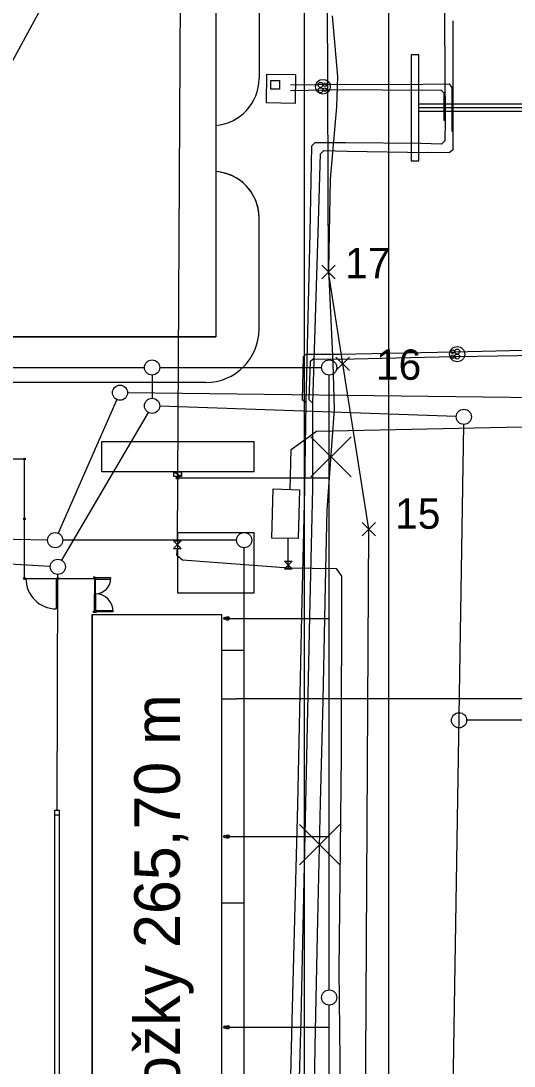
# Model space of a CAD drawing. Extents: x -264095 to -263675, y -1242370 to -1242073.
# Drawn here: x -263972.3 to -263939.8, y -1242227.5 to -1242158.7 of the extents above; entities that cross this region are included whole.
import ezdxf

# ---------------------------------------------------------------- set-up
doc = ezdxf.new("R2010")
doc.units = 0
for name, color, linetype in [('BODY', 7, 'Continuous'), ('KFA_2D_JESTVUJUCE_IS_DSP', 7, 'Continuous'), ('KFA_2D_SITUACIA_DSP', 7, 'Continuous'), ('ORANGE_KABEL_NOVA_TRASA', 7, 'Continuous'), ('POPIS', 7, 'Continuous'), ('Pripojka_NN_pre_ORANGE_vysielac_povodna_trasa', 7, 'Continuous')]:
    doc.layers.add(name, color=color, linetype=linetype)

msp = doc.modelspace()

# ---------------------------------------------------------------- linework, layer by layer
at = {"layer": 'BODY'}
for p, q in [((-263952.482, -1242175.643), (-263951.598, -1242174.759)), ((-263951.598, -1242175.643), (-263952.482, -1242174.759)), ((-263951.549, -1242181.696), (-263950.665, -1242180.812)), ((-263950.665, -1242181.696), (-263951.549, -1242180.812)), ((-263949.826, -1242192.601), (-263948.942, -1242191.717)), ((-263948.942, -1242192.601), (-263949.826, -1242191.717))]:
    msp.add_line(p, q, dxfattribs=at)
at = {"layer": 'KFA_2D_JESTVUJUCE_IS_DSP'}
for p, q in [((-263961.582, -1242115.554), (-263961.999, -1242192.922)), ((-263944.386, -1242147.884), (-263944.412, -1242158.664)), ((-263944.412, -1242158.664), (-263944.352, -1242165.249)), ((-263943.853, -1242158.652), (-263943.849, -1242165.958)), ((-263956.13, -1242162.18), (-263956.156, -1242164.04)), ((-263954.192, -1242162.207), (-263956.13, -1242162.18)), ((-263954.218, -1242164.067), (-263954.192, -1242162.207)), ((-263955.831, -1242163.152), (-263955.831, -1242162.573)), ((-263955.831, -1242162.573), (-263955.28, -1242162.573)), ((-263955.28, -1242162.573), (-263955.28, -1242163.152)), ((-263951.019, -1242162.854), (-263954.543, -1242162.888)), ((-263951.019, -1242162.854), (-263945.83, -1242162.832)), ((-263945.83, -1242162.832), (-263944.071, -1242162.801)), ((-263943.916, -1242163.012), (-263944.071, -1242162.801)), ((-263955.28, -1242163.152), (-263955.831, -1242163.152)), ((-263951.079, -1242163.196), (-263954.539, -1242163.255)), ((-263945.899, -1242163.231), (-263951.079, -1242163.196)), ((-263944.614, -1242163.211), (-263945.899, -1242163.231)), ((-263944.447, -1242163.393), (-263944.614, -1242163.211)), ((-263944.447, -1242163.393), (-263944.442, -1242165.164)), ((-263943.914, -1242163.012), (-263943.913, -1242165.895)), ((-263956.156, -1242164.04), (-263954.218, -1242164.067)), ((-263944.442, -1242165.164), (-263944.352, -1242165.249)), ((-263944.442, -1242165.164), (-263944.442, -1242165.164)), ((-263944.352, -1242165.249), (-263944.379, -1242166.564)), ((-263943.913, -1242165.895), (-263943.849, -1242165.958)), ((-263943.913, -1242165.895), (-263943.913, -1242165.895)), ((-263943.849, -1242165.958), (-263943.861, -1242167.143)), ((-263953.167, -1242166.907), (-263953.276, -1242172.621)), ((-263952.942, -1242166.698), (-263953.167, -1242166.907)), ((-263950.896, -1242166.694), (-263952.942, -1242166.698)), ((-263945.968, -1242166.741), (-263950.896, -1242166.694)), ((-263944.61, -1242166.777), (-263945.968, -1242166.741)), ((-263944.379, -1242166.564), (-263944.61, -1242166.777)), ((-263952.715, -1242172.612), (-263952.57, -1242167.416)), ((-263952.57, -1242167.416), (-263952.361, -1242167.2)), ((-263952.361, -1242167.2), (-263950.803, -1242167.244)), ((-263950.803, -1242167.244), (-263945.525, -1242167.325)), ((-263944.087, -1242167.347), (-263945.525, -1242167.325)), ((-263943.861, -1242167.143), (-263944.087, -1242167.347)), ((-263953.276, -1242172.621), (-263953.528, -1242183.799)), ((-263953.067, -1242183.845), (-263952.715, -1242172.612)), ((-263943.779, -1242180.456), (-263932.226, -1242180.187)), ((-263953.71, -1242180.8), (-263953.774, -1242183.629)), ((-263953.71, -1242180.8), (-263953.518, -1242180.617)), ((-263953.518, -1242180.617), (-263951.311, -1242180.614)), ((-263951.311, -1242180.614), (-263943.779, -1242180.456)), ((-263951.265, -1242180.941), (-263943.848, -1242180.778)), ((-263943.848, -1242180.778), (-263943.567, -1242180.776)), ((-263943.567, -1242180.776), (-263932.313, -1242180.597)), ((-263953.31, -1242183.629), (-263953.231, -1242181.09)), ((-263953.231, -1242181.09), (-263953.049, -1242180.917)), ((-263953.049, -1242180.917), (-263951.265, -1242180.941)), ((-263965.974, -1242183.616), (-263969.841, -1242192.426)), ((-263923.234, -1242183.668), (-263965.273, -1242183.165)), ((-263953.528, -1242183.799), (-263953.774, -1242183.629)), ((-263953.067, -1242183.845), (-263953.31, -1242183.629)), ((-263943.628, -1242184.728), (-263963.161, -1242184.046)), ((-263953.528, -1242183.799), (-263953.63, -1242189.514)), ((-263953.083, -1242189.456), (-263953.067, -1242183.845)), ((-263963.914, -1242184.46), (-263969.615, -1242194.201)), ((-263954.509, -1242186.913), (-263952.832, -1242185.692)), ((-263952.832, -1242185.692), (-263937.488, -1242185.363)), ((-263943.946, -1242236.311), (-263943.136, -1242185.245)), ((-263954.57, -1242189.535), (-263954.509, -1242186.913)), ((-263955.775, -1242192.739), (-263955.679, -1242189.503)), ((-263955.679, -1242189.503), (-263953.955, -1242189.552)), ((-263953.955, -1242189.552), (-263954.033, -1242192.766)), ((-263953.63, -1242189.514), (-263953.822, -1242197.849)), ((-263953.266, -1242197.902), (-263953.083, -1242189.456)), ((-263970.367, -1242194.605), (-264044.102, -1242190.483)), ((-263970.542, -1242192.875), (-264044.328, -1242191.641)), ((-263962.251, -1242192.922), (-263961.751, -1242192.922)), ((-263961.751, -1242192.922), (-263962.251, -1242193.422)), ((-263961.751, -1242193.422), (-263962.251, -1242192.922)), ((-263954.033, -1242192.766), (-263955.775, -1242192.739)), ((-263954.693, -1242194.518), (-263954.696, -1242192.756)), ((-263962.251, -1242193.422), (-263961.751, -1242193.422)), ((-263962.017, -1242193.422), (-263962.046, -1242193.838)), ((-263962.046, -1242193.838), (-263961.65, -1242194.164)), ((-263961.65, -1242194.164), (-263954.663, -1242194.7)), ((-263954.943, -1242194.268), (-263954.443, -1242194.268)), ((-263954.443, -1242194.268), (-263954.943, -1242194.768)), ((-263954.443, -1242194.768), (-263954.943, -1242194.268)), ((-263954.663, -1242194.7), (-263954.693, -1242194.518)), ((-263954.943, -1242194.768), (-263954.443, -1242194.768)), ((-263954.663, -1242194.7), (-263951.539, -1242194.754)), ((-263951.539, -1242194.754), (-263951.176, -1242195.243)), ((-263951.176, -1242195.243), (-263951.207, -1242207.105)), ((-263953.822, -1242197.849), (-263954.091, -1242210.31)), ((-263953.525, -1242210.24), (-263953.266, -1242197.902)), ((-263951.207, -1242207.105), (-263951.356, -1242221.201)), ((-263954.091, -1242210.31), (-263954.451, -1242224.536)), ((-263953.851, -1242224.476), (-263953.525, -1242210.24)), ((-263951.356, -1242221.201), (-263951.228, -1242233.09)), ((-263954.451, -1242224.536), (-263954.692, -1242233.447)), ((-263954.106, -1242234.073), (-263953.851, -1242224.476))]:
    msp.add_line(p, q, dxfattribs=at)
for centre, radius in [((-263952.413, -1242162.992), 0.487), ((-263952.568, -1242162.867), 0.164), ((-263952.284, -1242162.851), 0.122), ((-263952.568, -1242163.22), 0.164), ((-263952.284, -1242163.187), 0.122), ((-263943.568, -1242180.617), 0.496), ((-263943.848, -1242180.461), 0.122), ((-263943.848, -1242180.778), 0.122), ((-263943.567, -1242180.445), 0.164), ((-263943.567, -1242180.776), 0.164), ((-263965.773, -1242183.159), 0.5), ((-263963.661, -1242184.028), 0.5), ((-263943.128, -1242184.745), 0.5), ((-263970.042, -1242192.883), 0.5), ((-263969.868, -1242194.633), 0.5)]:
    msp.add_circle(centre, radius, dxfattribs=at)
at = {"layer": 'KFA_2D_SITUACIA_DSP'}
for p, q in [((-263959.468, -1242072.525), (-263959.468, -1242179.482)), ((-263948.093, -1242087.901), (-263948.093, -1242241.458)), ((-263953.617, -1242244.458), (-263953.617, -1242093.307)), ((-263956.618, -1242127.418), (-263956.618, -1242162.449)), ((-263918.489, -1242164.132), (-263946.093, -1242164.132)), ((-263918.593, -1242164.382), (-263946.093, -1242164.382)), ((-263918.696, -1242164.632), (-263946.093, -1242164.632)), ((-263959.468, -1242165.549), (-263959.468, -1242165.549)), ((-263959.467, -1242168.582), (-263959.467, -1242168.582)), ((-263956.618, -1242178.982), (-263956.618, -1242171.645)), ((-264095.114, -1242179.482), (-263959.468, -1242179.482)), ((-263959.468, -1242179.482), (-264095.114, -1242179.482)), ((-263959.468, -1242179.482), (-264077.23, -1242179.482)), ((-263956.618, -1242178.982), (-263956.618, -1242178.982)), ((-264013.161, -1242181.5), (-263964.161, -1242181.5)), ((-263963.161, -1242181.5), (-263952.5, -1242181.5)), ((-263963.661, -1242182), (-263963.661, -1242183.528)), ((-263952, -1242222.527), (-263952, -1242182)), ((-263960.118, -1242182.482), (-264034.158, -1242182.482)), ((-263972.068, -1242187.532), (-264095.114, -1242187.532)), ((-263972.128, -1242187.532), (-263972.008, -1242187.532)), ((-263972.068, -1242187.592), (-263972.068, -1242187.472)), ((-263972.068, -1242195.407), (-263972.068, -1242187.532)), ((-263962.218, -1242188.382), (-263961.718, -1242188.382)), ((-263962.218, -1242188.672), (-263962.218, -1242188.382)), ((-263962.218, -1242188.382), (-263961.718, -1242188.672)), ((-263962.218, -1242188.382), (-263961.718, -1242188.672)), ((-263961.718, -1242188.382), (-263962.218, -1242188.382)), ((-263961.718, -1242188.382), (-263961.718, -1242188.672)), ((-263961.718, -1242188.672), (-263961.718, -1242188.382)), ((-263961.718, -1242188.672), (-263962.218, -1242188.672)), ((-263961.868, -1242188.772), (-263952, -1242188.772)), ((-263972.128, -1242191.47), (-263972.008, -1242191.47)), ((-263972.068, -1242191.41), (-263972.068, -1242191.53)), ((-263958.097, -1242192.883), (-263969.542, -1242192.883)), ((-263957.597, -1242243.932), (-263957.597, -1242193.383)), ((-263969.921, -1242210.683), (-263969.869, -1242195.133)), ((-263967.413, -1242195.307), (-263967.513, -1242195.307)), ((-263967.513, -1242195.307), (-263967.513, -1242195.407)), ((-263967.425, -1242195.32), (-263967.5, -1242195.32)), ((-263967.5, -1242195.32), (-263967.5, -1242195.395)), ((-263967.425, -1242195.395), (-263967.425, -1242195.32)), ((-263967.425, -1242195.395), (-263967.425, -1242195.345)), ((-263967.425, -1242195.345), (-263967.325, -1242195.345)), ((-263967.413, -1242195.407), (-263967.413, -1242195.307)), ((-263967.413, -1242195.357), (-263967.363, -1242195.357)), ((-263967.363, -1242195.357), (-263967.363, -1242195.457)), ((-263967.325, -1242195.345), (-263967.325, -1242195.37)), ((-263972.068, -1242195.407), (-263967.418, -1242195.407)), ((-263969.968, -1242195.407), (-263969.968, -1242197.407)), ((-263967.513, -1242195.407), (-263967.413, -1242195.407)), ((-263967.5, -1242195.395), (-263967.425, -1242195.395)), ((-263967.463, -1242195.407), (-263967.463, -1242196.395)), ((-263967.388, -1242195.407), (-263967.463, -1242195.407)), ((-263967.388, -1242196.395), (-263967.388, -1242195.407)), ((-263967.363, -1242195.457), (-263967.388, -1242195.457)), ((-263966.388, -1242195.371), (-263967.375, -1242195.37)), ((-263967.375, -1242195.37), (-263967.375, -1242195.445)), ((-263967.375, -1242195.445), (-263966.388, -1242195.446)), ((-263967.463, -1242197.557), (-263967.463, -1242196.42)), ((-263967.388, -1242196.42), (-263967.388, -1242197.557)), ((-263967.593, -1242252.182), (-263967.593, -1242197.782)), ((-263967.593, -1242197.782), (-263959.093, -1242197.782)), ((-263967.593, -1242197.782), (-263959.097, -1242197.782)), ((-263967.593, -1242252.182), (-263967.593, -1242197.782)), ((-263967.513, -1242197.557), (-263967.413, -1242197.557)), ((-263967.513, -1242197.657), (-263967.513, -1242197.557)), ((-263967.413, -1242197.657), (-263967.513, -1242197.657)), ((-263967.5, -1242197.57), (-263967.425, -1242197.57)), ((-263967.5, -1242197.645), (-263967.5, -1242197.57)), ((-263967.425, -1242197.645), (-263967.5, -1242197.645)), ((-263967.478, -1242197.782), (-263967.358, -1242197.782)), ((-263967.388, -1242197.557), (-263967.463, -1242197.557)), ((-263967.425, -1242197.57), (-263967.425, -1242197.62)), ((-263967.425, -1242197.57), (-263967.425, -1242197.645)), ((-263967.425, -1242197.62), (-263967.325, -1242197.62)), ((-263967.413, -1242197.557), (-263967.413, -1242197.657)), ((-263967.413, -1242197.607), (-263967.363, -1242197.607)), ((-263967.363, -1242197.507), (-263967.388, -1242197.507)), ((-263967.375, -1242197.52), (-263966.238, -1242197.52)), ((-263967.375, -1242197.595), (-263967.375, -1242197.52)), ((-263966.238, -1242197.595), (-263967.375, -1242197.595)), ((-263967.363, -1242197.607), (-263967.363, -1242197.507)), ((-263967.325, -1242197.62), (-263967.325, -1242197.595)), ((-263959.097, -1242197.782), (-263959.093, -1242252.182)), ((-263959.093, -1242197.782), (-263959.093, -1242252.182)), ((-263958.799, -1242197.962), (-263958.762, -1242197.962)), ((-263958.799, -1242198.102), (-263958.762, -1242198.102)), ((-263958.762, -1242197.962), (-263958.742, -1242197.942)), ((-263958.762, -1242198.102), (-263958.742, -1242198.122)), ((-263958.742, -1242197.942), (-263958.637, -1242197.942)), ((-263958.575, -1242198.032), (-263952, -1242198.032)), ((-263958.742, -1242198.122), (-263958.637, -1242198.122)), ((-263959.097, -1242200.132), (-263957.597, -1242200.132)), ((-263959.097, -1242203.332), (-263958.097, -1242203.332)), ((-263924.893, -1242203.332), (-263958.097, -1242203.332)), ((-263938.393, -1242204.752), (-263942.945, -1242204.752)), ((-263970.071, -1242210.684), (-263969.77, -1242210.682)), ((-263970.07, -1242239.282), (-263970.071, -1242210.684)), ((-263970.071, -1242210.983), (-263969.771, -1242210.985)), ((-263969.77, -1242210.682), (-263969.77, -1242239.282)), ((-263958.799, -1242212.337), (-263958.762, -1242212.337)), ((-263958.799, -1242212.477), (-263958.762, -1242212.477)), ((-263958.762, -1242212.337), (-263958.742, -1242212.317)), ((-263958.762, -1242212.477), (-263958.742, -1242212.497)), ((-263958.742, -1242212.317), (-263958.637, -1242212.317)), ((-263958.742, -1242212.497), (-263958.637, -1242212.497)), ((-263958.575, -1242212.407), (-263952, -1242212.407)), ((-263959.097, -1242216.782), (-263957.597, -1242216.782)), ((-263952, -1242251.432), (-263952, -1242223.527)), ((-263958.799, -1242224.912), (-263958.762, -1242224.912)), ((-263958.762, -1242224.912), (-263958.742, -1242224.892)), ((-263958.742, -1242224.892), (-263958.637, -1242224.892)), ((-263958.575, -1242224.982), (-263952, -1242224.982)), ((-263958.799, -1242225.052), (-263958.762, -1242225.052)), ((-263958.762, -1242225.052), (-263958.742, -1242225.072)), ((-263958.742, -1242225.072), (-263958.637, -1242225.072))]:
    msp.add_line(p, q, dxfattribs=at)
for points in [[(-263946.093, -1242167.882), (-263946.093, -1242160.882), (-263946.593, -1242160.882), (-263946.593, -1242167.882)], [(-263966.968, -1242186.382), (-263956.968, -1242186.382), (-263956.968, -1242188.382), (-263966.968, -1242188.382)], [(-263961.968, -1242192.382), (-263956.968, -1242192.382), (-263956.968, -1242196.382), (-263961.968, -1242196.382)], [(-263967.597, -1242197.782), (-263959.097, -1242197.782), (-263959.097, -1242252.182), (-263967.597, -1242252.182)]]:
    msp.add_lwpolyline(points, close=True, dxfattribs=at)
msp.add_lwpolyline([(-263956.618, -1242178.982), (-263956.618, -1242171.626), (-263956.64, -1242171.257), (-263956.707, -1242170.894), (-263956.87, -1242170.411), (-263957.158, -1242169.893), (-263957.435, -1242169.549), (-263957.705, -1242169.291), (-263958.077, -1242169.024), (-263958.45, -1242168.829), (-263958.842, -1242168.69), (-263959.056, -1242168.638), (-263959.273, -1242168.601), (-263959.468, -1242168.582)], dxfattribs=at)
for centre, radius in [((-263963.661, -1242181.5), 0.5), ((-263952, -1242181.5), 0.5), ((-263972.068, -1242187.532), 0.06), ((-263961.968, -1242188.772), 0.1), ((-263972.068, -1242191.47), 0.06), ((-263957.597, -1242192.883), 0.5), ((-263969.868, -1242194.633), 0.5), ((-263972.068, -1242195.407), 0.06), ((-263969.868, -1242195.407), 0.06), ((-263958.847, -1242198.032), 0.085), ((-263958.847, -1242198.032), 0.0625), ((-263958.637, -1242198.032), 0.0625), ((-263943.445, -1242204.752), 0.5), ((-263958.847, -1242212.407), 0.085), ((-263958.847, -1242212.407), 0.0625), ((-263958.637, -1242212.407), 0.0625), ((-263952, -1242223.027), 0.5), ((-263958.847, -1242224.982), 0.085), ((-263958.847, -1242224.982), 0.0625), ((-263958.637, -1242224.982), 0.0625)]:
    msp.add_circle(centre, radius, dxfattribs=at)
for centre, radius, start, end in [((-263959.738, -1242162.441), 3.12, 274.96374, 359.8482), ((-263959.668, -1242171.626), 3.05, 359.64411, 86.21555), ((-263960.118, -1242178.982), 3.5, 270, 0), ((-263969.968, -1242195.407), 2, 180, 270), ((-263967.4, -1242195.382), 1.025, 270.60954, 0.60953), ((-263967.4, -1242197.582), 1.175, 359.39047, 89.39046), ((-263958.637, -1242198.032), 0.09, 270, 90), ((-263958.637, -1242212.407), 0.09, 270, 90), ((-263958.637, -1242224.982), 0.09, 270, 90)]:
    msp.add_arc(centre, radius, start, end, dxfattribs=at)
for centre in [(-263967.4, -1242195.382), (-263967.4, -1242195.382), (-263967.4, -1242197.582)]:
    msp.add_ellipse(centre, major_axis=(0, 0.0125), ratio=0.999995, dxfattribs=at)
at = {"layer": 'ORANGE_KABEL_NOVA_TRASA'}
msp.add_line((-263952.04, -1242175.201), (-263952.166, -1242145.743), dxfattribs=at)
msp.add_lwpolyline([(-264024.488, -1242318.06), (-264024.034, -1242317.042), (-264023.371, -1242316.883), (-264019.944, -1242316.823), (-264007.092, -1242316.551), (-263992.063, -1242316.466), (-263977.145, -1242316.356), (-263964.015, -1242316.054), (-263949.321, -1242315.778), (-263948.851, -1242315.553), (-263948.88, -1242313.336), (-263948.91, -1242263.218), (-263949.459, -1242259.659), (-263949.684, -1242246.614), (-263949.384, -1242192.159), (-263951.107, -1242181.254), (-263952.04, -1242175.201)], dxfattribs=at)
at = {"layer": 'POPIS'}
msp.add_line((-263954.315, -1242127.178), (-263975.069, -1242165.345), dxfattribs=at)
at = {"layer": 'Pripojka_NN_pre_ORANGE_vysielac_povodna_trasa'}
for p, q in [((-263953.196, -1242188.714), (-263950.544, -1242186.062)), ((-263950.544, -1242188.714), (-263953.196, -1242186.062)), ((-263953.959, -1242214.272), (-263951.307, -1242211.62)), ((-263951.307, -1242214.272), (-263953.959, -1242211.62))]:
    msp.add_line(p, q, dxfattribs=at)
msp.add_lwpolyline([(-263954.154, -1242266.219), (-263954.181, -1242259.421), (-263953.291, -1242250.714), (-263953.128, -1242246.081), (-263953.003, -1242239.508), (-263953.042, -1242234.581), (-263952.925, -1242226.293), (-263952.76, -1242218.883), (-263952.574, -1242210.195), (-263952.394, -1242203.456), (-263952.216, -1242194.818), (-263952.122, -1242190.878), (-263951.644, -1242184.248), (-263951.726, -1242181.217), (-263952.029, -1242175.038), (-263951.914, -1242169.082), (-263951.489, -1242164.316), (-263951.418, -1242162.319), (-263951.777, -1242158.32)], dxfattribs=at)

# ---------------------------------------------------------------- texts
at = {"layer": 'BODY'}
for s, p in [('17', (-263950.942, -1242175.612)), ('16', (-263948.911, -1242182.308)), ('15', (-263947.65, -1242192.127))]:
    msp.add_text(s, height=2, dxfattribs=at).set_placement(p)
at = {"layer": 'POPIS'}
msp.add_text('dĺžka preložky 265,70 m', height=3, rotation=90, dxfattribs=at).set_placement((-263961.831, -1242246.288))

doc.saveas('drawing.dxf')
